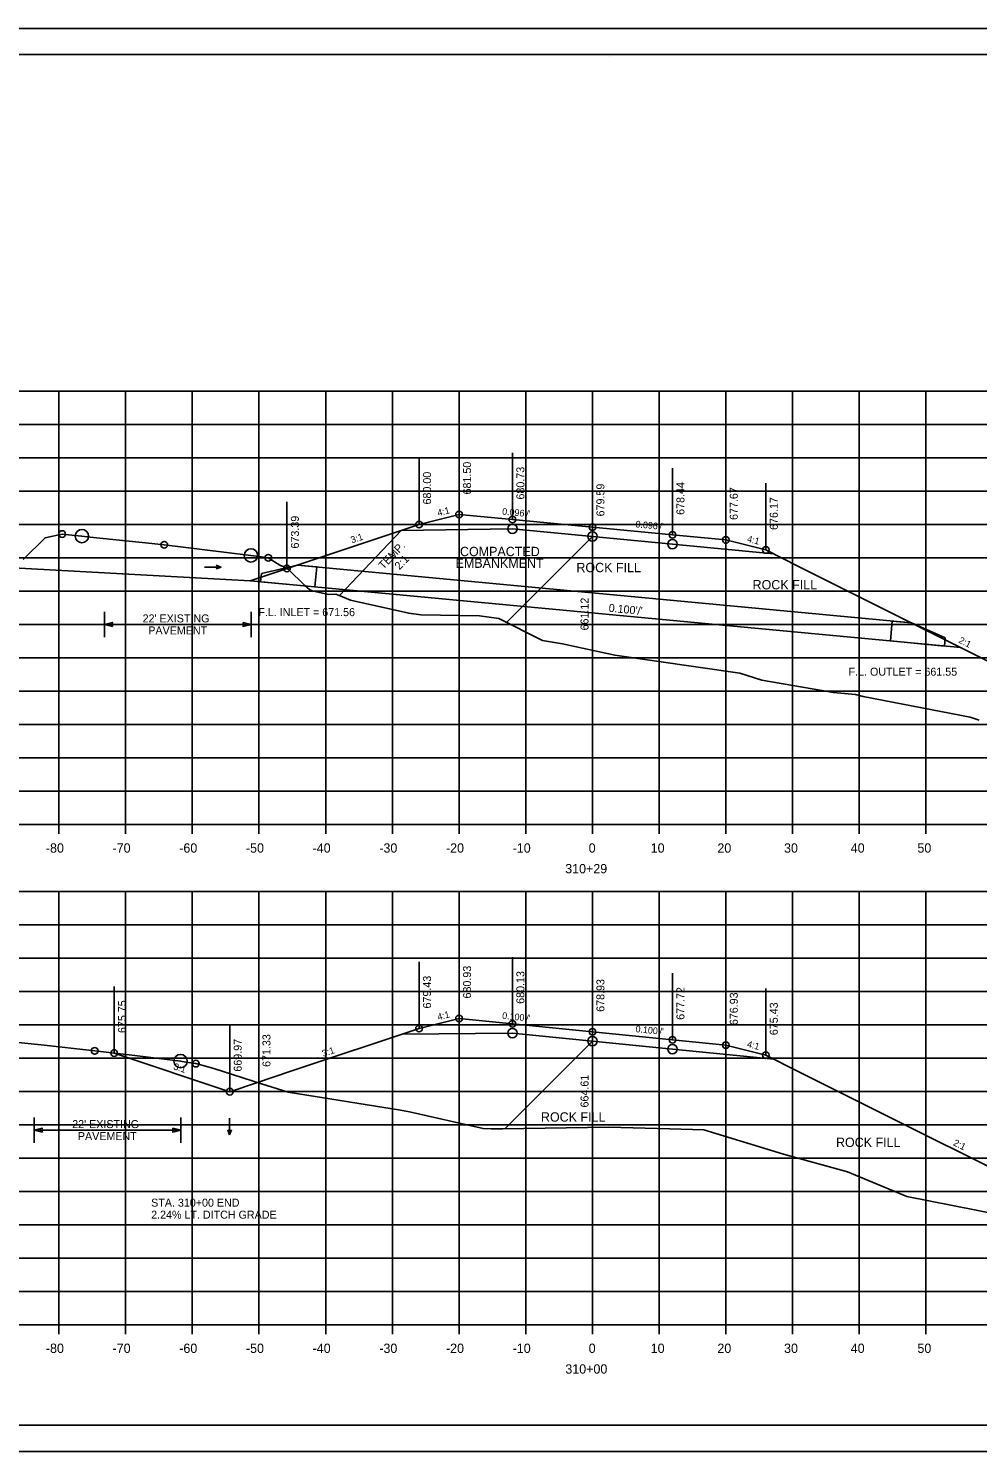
# Model space of a CAD drawing. Extents: x 1370515 to 1370849, y 383299 to 386073.
# Drawn here: x 1370593.2 to 1370735.6, y 384792.8 to 385006.1 of the extents above; entities that cross this region are included whole.
import ezdxf

# ---------------------------------------------------------------- set-up
doc = ezdxf.new("R2010")
doc.units = 0
for name, color, linetype in [('R_Alt Surface', 7, 'Continuous'), ('R_Axis', 7, 'Continuous'), ('R_Axis Annot', 7, 'Continuous'), ('R_Border', 7, 'Continuous'), ('R_Detour', 7, 'Continuous'), ('R_Drive', 7, 'Continuous'), ('R_Exist Surface', 7, 'Continuous'), ('R_Fin Surface', 7, 'Continuous'), ('R_Grid', 7, 'Continuous'), ('R_No Plot', 7, 'Continuous'), ('R_ROW Annot', 7, 'Continuous'), ('R_Water', 7, 'Continuous'), ('R_Water Annot', 7, 'Continuous'), ('R_Xsect Elev', 7, 'Continuous'), ('R_Xsect Slope', 7, 'Continuous')]:
    doc.layers.add(name, color=color, linetype=linetype)

msp = doc.modelspace()

# ---------------------------------------------------------------- linework, layer by layer
at = {"layer": 'R_Alt Surface'}
for points in [[(1370649.12, 384930.88), (1370665.8, 384931.13), (1370677.8, 384929.98), (1370689.8, 384928.83), (1370704.95, 384927.37)], [(1370649.21, 384855.35), (1370665.8, 384855.53), (1370677.8, 384854.33), (1370689.8, 384853.13), (1370705.03, 384851.59)]]:
    msp.add_lwpolyline(points, dxfattribs=at)
at = {"layer": 'R_Axis'}
for p, q in [((1370537.8, 384886.77), (1370817.8, 384886.77)), ((1370597.8, 384885.37), (1370597.8, 384888.17)), ((1370607.8, 384885.37), (1370607.8, 384888.17)), ((1370617.8, 384885.37), (1370617.8, 384888.17)), ((1370627.8, 384885.37), (1370627.8, 384888.17)), ((1370637.8, 384885.37), (1370637.8, 384888.17)), ((1370647.8, 384885.37), (1370647.8, 384888.17)), ((1370657.8, 384885.37), (1370657.8, 384888.17)), ((1370667.8, 384885.37), (1370667.8, 384888.17)), ((1370677.8, 384885.37), (1370677.8, 384888.17)), ((1370687.8, 384885.37), (1370687.8, 384888.17)), ((1370697.8, 384885.37), (1370697.8, 384888.17)), ((1370707.8, 384885.37), (1370707.8, 384888.17)), ((1370717.8, 384885.37), (1370717.8, 384888.17)), ((1370727.8, 384885.37), (1370727.8, 384888.17)), ((1370597.8, 384810.37), (1370597.8, 384813.17)), ((1370607.8, 384810.37), (1370607.8, 384813.17)), ((1370617.8, 384810.37), (1370617.8, 384813.17)), ((1370627.8, 384810.37), (1370627.8, 384813.17)), ((1370637.8, 384810.37), (1370637.8, 384813.17)), ((1370647.8, 384810.37), (1370647.8, 384813.17)), ((1370657.8, 384810.37), (1370657.8, 384813.17)), ((1370667.8, 384810.37), (1370667.8, 384813.17)), ((1370677.8, 384810.37), (1370677.8, 384813.17)), ((1370687.8, 384810.37), (1370687.8, 384813.17)), ((1370697.8, 384810.37), (1370697.8, 384813.17)), ((1370707.8, 384810.37), (1370707.8, 384813.17)), ((1370717.8, 384810.37), (1370717.8, 384813.17)), ((1370727.8, 384810.37), (1370727.8, 384813.17)), ((1370537.8, 384811.77), (1370817.8, 384811.77))]:
    msp.add_line(p, q, dxfattribs=at)
at = {"layer": 'R_Border'}
for p, q in [((1370527.8, 385002.23), (1370843.98, 385002.23)), ((1370680.32, 385001.97), (1370680.32, 385001.97)), ((1370680.32, 385001.97), (1370680.32, 385001.97)), ((1370843.98, 384796.77), (1370527.8, 384796.77))]:
    msp.add_line(p, q, dxfattribs=at)
at = {"layer": 'R_Detour'}
msp.add_line((1370649.12, 384930.88), (1370639.86, 384921.1), dxfattribs=at)
at = {"layer": 'R_Exist Surface'}
for points in [[(1370592.43, 384926.52), (1370595.72, 384929.79), (1370597.76, 384930.23), (1370598.29, 384930.34), (1370601.19, 384930.04), (1370601.25, 384930.03), (1370602.47, 384929.89), (1370611.74, 384928.9), (1370613.6, 384928.73), (1370622.51, 384927.6), (1370626.6, 384927.13), (1370627.76, 384926.97), (1370629.2, 384926.78), (1370630.95, 384925.66), (1370631.53, 384925.42), (1370632.17, 384925.07), (1370634.66, 384922.6), (1370635.35, 384922.04), (1370635.78, 384921.81), (1370638.23, 384921.27), (1370639.31, 384921.33), (1370640.33, 384920.9), (1370641.5, 384920.42), (1370650.26, 384918.47), (1370652.08, 384918.23), (1370660.87, 384918.06), (1370663.75, 384917.69), (1370670.34, 384914.36), (1370673.3, 384913.88), (1370681.17, 384912.16), (1370699.89, 384909.46), (1370703.22, 384908.45), (1370713.93, 384906.57), (1370717.26, 384906.3), (1370718.42, 384905.98), (1370734.44, 384902.89), (1370735.82, 384902.41)], [(1370591.2, 384854.18), (1370595.11, 384853.75), (1370603.16, 384852.86), (1370609.2, 384852.16), (1370616.04, 384851.32), (1370616.84, 384851.17), (1370618.33, 384850.94), (1370619.77, 384850.58), (1370621.04, 384850.2), (1370628.17, 384847.9), (1370632.19, 384846.65), (1370649.01, 384843.95), (1370650.35, 384843.71), (1370661.41, 384841.21), (1370662.61, 384841.16), (1370664.35, 384841.16), (1370680.23, 384841.42), (1370689.4, 384841.16), (1370694.5, 384841.01), (1370706.47, 384837.39), (1370716.07, 384834.74), (1370724.94, 384831.01), (1370738.9, 384828.29)]]:
    msp.add_lwpolyline(points, dxfattribs=at)
at = {"layer": 'R_Fin Surface'}
for p, q in [((1370677.82, 384929.97), (1370664.94, 384917.09)), ((1370677.82, 384854.32), (1370664.66, 384841.16))]:
    msp.add_line(p, q, dxfattribs=at)
for points in [[(1370588.17, 384925.44), (1370626.49, 384923.33), (1370651.8, 384931.77), (1370657.8, 384933.27), (1370665.8, 384932.51), (1370677.8, 384931.36), (1370689.8, 384930.21), (1370697.8, 384929.45), (1370703.8, 384927.95), (1370708.72, 384925.49), (1370755.19, 384902.25)], [(1370606.07, 384852.53), (1370623.41, 384846.74), (1370627.3, 384848.02), (1370632.71, 384849.88), (1370651.8, 384856.21), (1370657.8, 384857.71), (1370665.8, 384856.91), (1370677.8, 384855.71), (1370689.8, 384854.51), (1370697.8, 384853.71), (1370703.8, 384852.21), (1370708.65, 384849.78), (1370753.58, 384827.32)]]:
    msp.add_lwpolyline(points, dxfattribs=at)
at = {"layer": 'R_Grid'}
for p, q in [((1370537.8, 384951.77), (1370817.8, 384951.77)), ((1370597.8, 384886.77), (1370597.8, 384951.77)), ((1370607.8, 384886.77), (1370607.8, 384951.77)), ((1370617.8, 384886.77), (1370617.8, 384951.77)), ((1370627.8, 384886.77), (1370627.8, 384951.77)), ((1370637.8, 384886.77), (1370637.8, 384951.77)), ((1370647.8, 384886.77), (1370647.8, 384951.77)), ((1370657.8, 384886.77), (1370657.8, 384951.77)), ((1370667.8, 384886.77), (1370667.8, 384951.77)), ((1370677.8, 384886.77), (1370677.8, 384951.77)), ((1370687.8, 384886.77), (1370687.8, 384951.77)), ((1370697.8, 384886.77), (1370697.8, 384951.77)), ((1370707.8, 384886.77), (1370707.8, 384951.77)), ((1370717.8, 384886.77), (1370717.8, 384951.77)), ((1370727.8, 384886.77), (1370727.8, 384951.77)), ((1370537.8, 384946.77), (1370817.8, 384946.77)), ((1370537.8, 384941.77), (1370817.8, 384941.77)), ((1370537.8, 384936.77), (1370817.8, 384936.77)), ((1370537.8, 384931.77), (1370817.8, 384931.77)), ((1370537.8, 384926.77), (1370817.8, 384926.77)), ((1370537.8, 384921.77), (1370817.8, 384921.77)), ((1370537.8, 384916.77), (1370817.8, 384916.77)), ((1370537.8, 384911.77), (1370817.8, 384911.77)), ((1370537.8, 384906.77), (1370817.8, 384906.77)), ((1370537.8, 384901.77), (1370817.8, 384901.77)), ((1370537.8, 384896.77), (1370817.8, 384896.77)), ((1370537.8, 384891.77), (1370817.8, 384891.77)), ((1370537.8, 384886.77), (1370817.8, 384886.77)), ((1370537.8, 384876.77), (1370817.8, 384876.77)), ((1370597.8, 384811.77), (1370597.8, 384876.77)), ((1370607.8, 384811.77), (1370607.8, 384876.77)), ((1370617.8, 384811.77), (1370617.8, 384876.77)), ((1370627.8, 384811.77), (1370627.8, 384876.77)), ((1370637.8, 384811.77), (1370637.8, 384876.77)), ((1370647.8, 384811.77), (1370647.8, 384876.77)), ((1370657.8, 384811.77), (1370657.8, 384876.77)), ((1370667.8, 384811.77), (1370667.8, 384876.77)), ((1370677.8, 384811.77), (1370677.8, 384876.77)), ((1370687.8, 384811.77), (1370687.8, 384876.77)), ((1370697.8, 384811.77), (1370697.8, 384876.77)), ((1370707.8, 384811.77), (1370707.8, 384876.77)), ((1370717.8, 384811.77), (1370717.8, 384876.77)), ((1370727.8, 384811.77), (1370727.8, 384876.77)), ((1370537.8, 384871.77), (1370817.8, 384871.77)), ((1370537.8, 384866.77), (1370817.8, 384866.77)), ((1370537.8, 384861.77), (1370817.8, 384861.77)), ((1370537.8, 384856.77), (1370817.8, 384856.77)), ((1370537.8, 384851.77), (1370817.8, 384851.77)), ((1370537.8, 384846.77), (1370817.8, 384846.77)), ((1370537.8, 384841.77), (1370817.8, 384841.77)), ((1370537.8, 384836.77), (1370817.8, 384836.77)), ((1370537.8, 384831.77), (1370817.8, 384831.77)), ((1370537.8, 384826.77), (1370817.8, 384826.77)), ((1370537.8, 384821.77), (1370817.8, 384821.77)), ((1370537.8, 384816.77), (1370817.8, 384816.77)), ((1370537.8, 384811.77), (1370817.8, 384811.77))]:
    msp.add_line(p, q, dxfattribs=at)
at = {"layer": 'R_No Plot'}
for p, q in [((1370515.4, 385006.13), (1370848.73, 385006.13)), ((1370515.4, 384792.8), (1370848.73, 384792.8))]:
    msp.add_line(p, q, dxfattribs=at)
for points in [[(1370515.39, 385006.13), (1370848.73, 385006.13), (1370848.73, 384792.79), (1370515.39, 384792.79)], [(1370761.72, 385002.23), (1370761.72, 384992.35), (1370797.45, 384992.35), (1370797.45, 384989.43), (1370820.65, 384989.43), (1370820.65, 384966.22), (1370843.98, 384966.22), (1370843.98, 384796.77), (1370527.8, 384796.77), (1370527.8, 385002.23)]]:
    msp.add_lwpolyline(points, close=True, dxfattribs=at)
for centre, radius in [((1370657.8, 384933.27), 0.5), ((1370651.8, 384931.77), 0.5), ((1370651.8, 384931.77), 0.5), ((1370665.8, 384931.13), 0.7), ((1370665.8, 384932.51), 0.5), ((1370677.8, 384931.36), 0.5), ((1370598.29, 384930.34), 0.5), ((1370601.25, 384930.03), 1), ((1370677.8, 384929.98), 0.7), ((1370677.8, 384929.98), 0.7), ((1370689.8, 384928.83), 0.7), ((1370689.8, 384930.21), 0.5), ((1370697.8, 384929.45), 0.5), ((1370613.6, 384928.73), 0.5), ((1370626.6, 384927.13), 1), ((1370629.2, 384926.78), 0.5), ((1370703.8, 384927.95), 0.5), ((1370703.8, 384927.95), 0.5), ((1370631.99, 384925.17), 0.5), ((1370657.8, 384857.71), 0.5), ((1370665.8, 384856.91), 0.5), ((1370651.8, 384856.21), 0.5), ((1370651.8, 384856.21), 0.5), ((1370665.8, 384855.53), 0.7), ((1370677.8, 384854.33), 0.7), ((1370677.8, 384854.33), 0.7), ((1370677.8, 384855.71), 0.5), ((1370689.8, 384854.51), 0.5), ((1370603.16, 384852.86), 0.5), ((1370606.07, 384852.53), 0.5), ((1370689.8, 384853.13), 0.7), ((1370697.8, 384853.71), 0.5), ((1370703.8, 384852.21), 0.5), ((1370703.8, 384852.21), 0.5), ((1370616.04, 384851.32), 1), ((1370618.33, 384850.94), 0.5), ((1370623.41, 384846.74), 0.5)]:
    msp.add_circle(centre, radius, dxfattribs=at)
at = {"layer": 'R_ROW Annot'}
for p, q in [((1370604.62, 384914.9), (1370604.62, 384918.67)), ((1370626.62, 384914.9), (1370626.62, 384918.67)), ((1370626.62, 384916.79), (1370604.62, 384916.79)), ((1370594.06, 384839.09), (1370594.06, 384842.86)), ((1370616.06, 384839.09), (1370616.06, 384842.86)), ((1370616.06, 384840.98), (1370594.06, 384840.98))]:
    msp.add_line(p, q, dxfattribs=at)
for points in [[(1370605.82, 384916.49), (1370604.62, 384916.79), (1370605.82, 384917.09)], [(1370625.42, 384917.09), (1370626.62, 384916.79), (1370625.42, 384916.49)], [(1370595.26, 384840.68), (1370594.06, 384840.98), (1370595.26, 384841.28)], [(1370614.86, 384841.28), (1370616.06, 384840.98), (1370614.86, 384840.68)]]:
    msp.add_lwpolyline(points, close=True, dxfattribs=at)
at = {"layer": 'R_Water'}
for p, q in [((1370633.56, 384925.68), (1370628.17, 384924.42)), ((1370725.65, 384917.02), (1370633.56, 384925.68)), ((1370636.45, 384925.4), (1370633.56, 384925.68)), ((1370636.17, 384922.42), (1370636.45, 384925.4)), ((1370733.07, 384913.31), (1370626.51, 384923.32)), ((1370628.05, 384923.18), (1370628.17, 384924.42)), ((1370636.17, 384922.42), (1370628.05, 384923.18)), ((1370722.48, 384914.31), (1370722.76, 384917.29)), ((1370722.76, 384917.29), (1370725.65, 384917.02)), ((1370725.65, 384917.02), (1370730.71, 384914.79)), ((1370730.59, 384913.55), (1370730.71, 384914.79)), ((1370722.48, 384914.31), (1370730.59, 384913.55))]:
    msp.add_line(p, q, dxfattribs=at)
at = {"layer": 'R_Water Annot'}
for p, q in [((1370619.64, 384925.39), (1370622.15, 384925.39)), ((1370622.15, 384925.39), (1370621.39, 384925.67)), ((1370622.15, 384925.39), (1370621.39, 384925.11)), ((1370623.4, 384842.77), (1370623.4, 384840.26)), ((1370623.4, 384840.26), (1370623.12, 384841.03)), ((1370623.4, 384840.26), (1370623.68, 384841.03))]:
    msp.add_line(p, q, dxfattribs=at)
at = {"layer": 'R_Xsect Elev'}
for p, q in [((1370657.8, 384933.27), (1370657.8, 384943.27)), ((1370665.8, 384932.51), (1370665.8, 384942.51)), ((1370651.8, 384931.77), (1370651.8, 384941.77)), ((1370677.8, 384929.98), (1370677.8, 384939.98)), ((1370689.8, 384930.21), (1370689.8, 384940.21)), ((1370697.8, 384929.45), (1370697.8, 384939.45)), ((1370703.8, 384927.95), (1370703.8, 384937.95)), ((1370631.99, 384925.17), (1370631.99, 384935.17)), ((1370677.82, 384912.89), (1370677.82, 384922.89)), ((1370657.8, 384857.71), (1370657.8, 384867.71)), ((1370651.8, 384856.21), (1370651.8, 384866.21)), ((1370665.8, 384856.91), (1370665.8, 384866.91)), ((1370677.8, 384855.71), (1370677.8, 384865.71)), ((1370689.8, 384854.51), (1370689.8, 384864.51)), ((1370697.8, 384853.71), (1370697.8, 384863.71)), ((1370606.07, 384852.53), (1370606.07, 384862.53)), ((1370703.8, 384852.21), (1370703.8, 384862.21)), ((1370623.41, 384846.74), (1370623.41, 384856.74)), ((1370677.82, 384841.37), (1370677.82, 384851.37))]:
    msp.add_line(p, q, dxfattribs=at)

# ---------------------------------------------------------------- texts
at = {"layer": 'R_Axis Annot'}
for s, p in [('COMPACTED', (1370657.94, 384927.02)), ('EMBANKMENT', (1370657.28, 384925.27)), ('ROCK FILL', (1370675.4, 384924.62)), ('ROCK FILL', (1370701.82, 384922.04)), ('-80', (1370595.84, 384882.57)), ('-70', (1370605.84, 384882.57)), ('-60', (1370615.84, 384882.57)), ('-50', (1370625.84, 384882.57)), ('-40', (1370635.84, 384882.57)), ('-30', (1370645.84, 384882.57)), ('-20', (1370655.84, 384882.57)), ('-10', (1370665.84, 384882.57)), ('0', (1370677.24, 384882.57)), ('10', (1370686.54, 384882.57)), ('20', (1370696.54, 384882.57)), ('30', (1370706.54, 384882.57)), ('40', (1370716.54, 384882.57)), ('50', (1370726.54, 384882.57)), ('310+29', (1370673.72, 384879.47)), ('ROCK FILL', (1370670.08, 384842.25)), ('ROCK FILL', (1370714.33, 384838.45)), ('-80', (1370595.84, 384807.57)), ('-70', (1370605.84, 384807.57)), ('-60', (1370615.84, 384807.57)), ('-50', (1370625.84, 384807.57)), ('-40', (1370635.84, 384807.57)), ('-30', (1370645.84, 384807.57)), ('-20', (1370655.84, 384807.57)), ('-10', (1370665.84, 384807.57)), ('0', (1370677.24, 384807.57)), ('10', (1370686.54, 384807.57)), ('20', (1370696.54, 384807.57)), ('30', (1370706.54, 384807.57)), ('40', (1370716.54, 384807.57)), ('50', (1370726.54, 384807.57)), ('310+00', (1370673.74, 384804.47))]:
    msp.add_text(s, height=1.4, dxfattribs=at).set_placement(p)
at = {"layer": 'R_Detour'}
for s, p in [('TEMP.', (1370646.46, 384924.95)), ('2:1', (1370648.87, 384924.88))]:
    msp.add_text(s, height=1.2, rotation=46.5651, dxfattribs=at).set_placement(p)
at = {"layer": 'R_Drive'}
for s, p in [('F.L. INLET = 671.56', (1370627.7, 384918.03)), ('F.L. OUTLET = 661.55', (1370716.22, 384909.1)), ('STA. 310+00 END', (1370611.63, 384829.5)), ('2.24% LT. DITCH GRADE', (1370611.63, 384827.7))]:
    msp.add_text(s, height=1.2, dxfattribs=at).set_placement(p)
at = {"layer": 'R_No Plot'}
for p in [(1370595.68, 384929.74), (1370632.13, 384925.02), (1370635.31, 384921.99), (1370641.46, 384920.37), (1370652.04, 384918.18), (1370713.89, 384906.52), (1370621, 384850.15), (1370632.15, 384846.6), (1370650.31, 384843.66), (1370664.31, 384841.11), (1370694.46, 384840.96), (1370724.89, 384830.96)]:
    msp.add_text('+', height=0.1, dxfattribs=at).set_placement(p)
at = {"layer": 'R_ROW Annot'}
for s, p in [("22' EXISTING", (1370610.35, 384917.09)), ('PAVEMENT', (1370611.2, 384915.29)), ("22' EXISTING", (1370599.79, 384841.28)), ('PAVEMENT', (1370600.64, 384839.48))]:
    msp.add_text(s, height=1.2, dxfattribs=at).set_placement(p)
at = {"layer": 'R_Xsect Elev'}
for s, p in [('681.50', (1370659.6, 384936.27)), ('680.73', (1370667.6, 384935.51)), ('680.00', (1370653.6, 384934.77)), ('678.44', (1370691.6, 384933.21)), ('679.59', (1370679.6, 384932.98)), ('677.67', (1370699.6, 384932.45)), ('676.17', (1370705.6, 384930.95)), ('673.39', (1370633.79, 384928.17)), ('661.12', (1370677.22, 384915.89)), ('680.93', (1370659.6, 384860.71)), ('679.43', (1370653.6, 384859.21)), ('680.13', (1370667.6, 384859.91)), ('678.93', (1370679.6, 384858.71)), ('677.72', (1370691.6, 384857.51)), ('676.93', (1370699.6, 384856.71)), ('675.75', (1370607.87, 384855.53)), ('675.43', (1370705.6, 384855.21)), ('671.33', (1370629.52, 384850.45)), ('669.97', (1370625.21, 384849.74)), ('664.61', (1370677.22, 384844.37))]:
    msp.add_text(s, height=1.2, rotation=90, dxfattribs=at).set_placement(p)
at = {"layer": 'R_Xsect Slope'}
for s, height, rotation, p in [('4:1', 1, 14.0362, (1370654.68, 384933.01)), ("0.096'/'", 1, 354.5359, (1370664.23, 384933.26)), ("0.096'/'", 1, 354.5359, (1370684.23, 384931.35)), ('3:1', 1, 18.4349, (1370641.74, 384928.94)), ('4:1', 1, 345.9638, (1370700.92, 384929.18)), ("0.100'/'", 1.2, 354.2894, (1370680.2, 384918.7)), ('2:1', 1, 333.4349, (1370732.63, 384914.09)), ('4:1', 1, 14.0362, (1370654.68, 384857.44)), ("0.100'/'", 1, 354.2894, (1370664.23, 384857.67)), ("0.100'/'", 1, 354.2894, (1370684.23, 384855.67)), ('3:1', 1, 18.4349, (1370637.45, 384851.95)), ('4:1', 1, 345.9638, (1370700.92, 384853.44)), ('3:1', 1, 341.5651, (1370614.9, 384850.11)), ('2:1', 1, 333.4349, (1370731.82, 384838.76))]:
    msp.add_text(s, height=height, rotation=rotation, dxfattribs=at).set_placement(p)

doc.saveas('drawing.dxf')
